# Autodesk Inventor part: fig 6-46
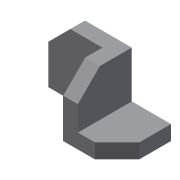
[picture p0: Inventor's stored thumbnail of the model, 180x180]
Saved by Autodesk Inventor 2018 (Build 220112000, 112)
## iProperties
Shininess: 77.0
Angle Display Precision: 2
Document Length Units: 11269
Document Angle Units: 11279
Document Time Units: 11290
Document Mass Units: 11283
Document Length Units Precision: 3
Document Angle Units Precision: 2
Created: 2001-12
Part Number: fig 6-46
Document SubType Name: Modeling
Designer: Renu Muthoo
Density: 1 g/cm^3
Material: Generic
Appearance: Default
Density: 0.0
Volumn: 0.0
Area: 0.0
PropertySet Name: Model Information
Control State: 0
Master: False
Checked Out: False
Author: Renu Muthoo
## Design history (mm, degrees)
node "Sketch1"
sketch "Sketch2"
  geometry: L1 (16.794, 27.142)-(16.794, -22.858); L2 (16.794, -22.858)-(-27.206, -22.858); L3 (-27.206, -22.858)-(-27.206, -10.858); L4 (-27.206, -10.858)-(4.794, -10.858); L5 (4.794, -10.858)-(4.794, 27.142); L6 (4.794, 27.142)-(16.794, 27.142)
  constraints: 12 end point, 4 parallel, 2 perpendicular, 1 vertical
  dimensions: "d0" = 44 distance of L1.end L2.end; "d1" = 50 distance of L1.start L1.end; "d2" = 12 distance of L2.end L3.end
extrude "Extrusion1" new body sketch "Sketch2" distance "d3" = 44; taper "d4" = 0 deg
sketch "Sketch4"
  geometry: L1 (-16.794, -27.142)-(-16.794, 22.858) reference; L2 (27.206, 22.858)-(27.206, 10.858) reference; L3 (-16.794, -27.142)-(-61.001, -27.142); L4 (-61.001, -27.142)-(-61.001, 22.858); L5 (-61.001, 22.858)-(-16.794, 22.858)
  constraints: 6 end point, 2 perpendicular, 1 parallel
extrude "Extrusion3" join sketch "Sketch4" distance "d13" = 12; taper "d14" = 0 deg
chamfer "Chamfer3" distance "d15" = 18; stored, may be unused: second distance "d16" = 2, angle "d17" = 45 deg
body "Solid1"
